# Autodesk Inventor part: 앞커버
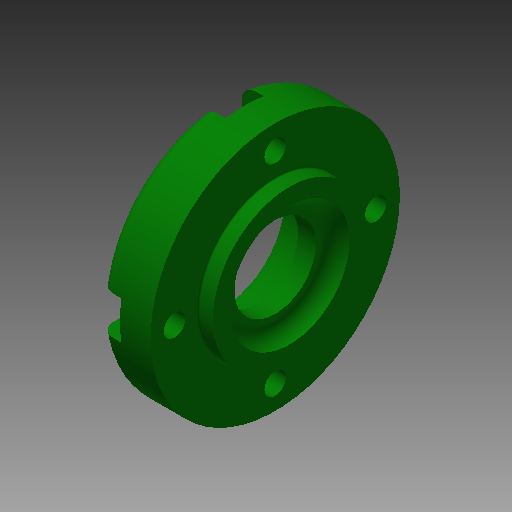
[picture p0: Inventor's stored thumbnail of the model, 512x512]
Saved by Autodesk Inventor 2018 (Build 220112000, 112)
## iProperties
Created: 2015-11
Part Number: 앞커버
Material: 알루미늄 6061
Document SubType Name: Modeling
Designer: mduedu
Density: 1 g/cm^3
Appearance: 진녹색
Author: mduedu
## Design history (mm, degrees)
sketch "스케치1"
  geometry: L1 (-7, 0)-(7, 0); L2 (-7, 0)-(-7, 26); L3 (-7, 26)-(4, 26); L4 (4, 26)-(4, 16); L5 (4, 16)-(7, 16); L6 (7, 16)-(7, 0); 2 further points
  constraints: 12 end point, 3 perpendicular, 2 parallel, 1 coincident, 1 horizontal, 1 midpoint
  dimensions: "d0" = 14 distance of L1.start L1.end; "d1" = 52 diameter of L3 L1; "d2" = 3 distance of L4.end L5.end; "d3" = 32 diameter of L5 L1
revolve "회전1" sketch "스케치1" stored, may be unused: angle "d4" = 90 deg
hole "구멍1" diameter "d7" = 25; stored, may be unused: countersink angle "d11" = 90 deg, drill point angle "d13" = 0 deg; dims "d5" = 10, "d6" = 10, "d8" = 6, "d9" = 4, "d10" = 2, "d12" = 3
hole "구멍2" diameter "d16" = 25; stored, may be unused: countersink angle "d20" = 90 deg, drill point angle "d22" = 0 deg; dims "d17" = 6, "d18" = 4, "d19" = 2, "d21" = 7.3, "d62" = 10, "d63" = 10
hole "구멍3" diameter "d25" = 17; stored, may be unused: countersink angle "d29" = 90 deg, drill point angle "d31" = 0 deg; dims "d23" = 10, "d24" = 10, "d26" = 6, "d27" = 4, "d28" = 2, "d30" = 4.2
chamfer "모따기1" distance "d32" = 0.7; stored, may be unused: second distance "d33" = 2, angle "d34" = 30 deg
fillet "모깎기1" dims "d35" = 0.3
fillet "모깎기2" dims "d36" = 3
fillet "모깎기3" dims "d37" = 3
fillet "모깎기4" dims "d38" = 0.3
sketch "스케치3" dims "d61" = 42
  geometry: C1 r 26 at (0, 0) reference; 2 further points
  constraints: 2 vertical alignment, 1 coincident, 2 other
hole "구멍4" sketch "스케치3" at (0, -21) diameter "d44" = 4.5; stored, may be unused: countersink angle "d48" = 90 deg, drill point angle "d50" = 0 deg; dims "d45" = 6, "d46" = 8, "d47" = 4.6, "d49" = 8
sketch "스케치4"
  geometry: L1 (-4, 0)-(-4, -4.69); L2 (4, 0)-(4, -4.69); A1 r 4 centre (0, 0) between (3.614, -1.714) and (-3.614, -1.714) reference; A2 r 26 centre (0, 21) between (-4, -4.69) and (4, -4.69) reference; 1 further point
  constraints: 4 end point, 4 point on circle, 2 tangent, 1 parallel, 1 vertical
extrude "돌출1" cut sketch "스케치4" extent not by distance; stored distance "d51" = 0; taper "d52" = 0 deg
node "솔리드1"
pattern_circular "원형 패턴1" dims angle "d54" = 360 deg
